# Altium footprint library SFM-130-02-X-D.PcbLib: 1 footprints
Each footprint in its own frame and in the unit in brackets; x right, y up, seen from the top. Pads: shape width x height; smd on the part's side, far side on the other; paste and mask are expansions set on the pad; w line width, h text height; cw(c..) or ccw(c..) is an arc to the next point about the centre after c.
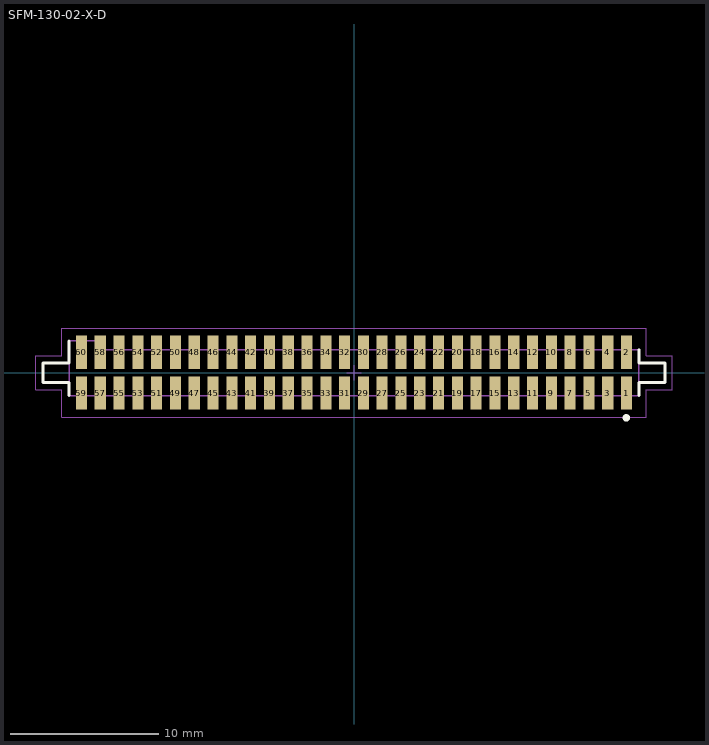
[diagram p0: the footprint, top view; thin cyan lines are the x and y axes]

## SFM-130-02-X-D [mm] "1.27mm pitch, 60 pin, socket header; SMT"
height 4.57
pads (60):
  rect 0.75x2.25 smd mask+0: 1(18.415,-1.375) 2(18.415,1.375) 3(17.145,-1.375) 4(17.145,1.375) 5(15.875,-1.375) 6(15.875,1.375) 7(14.605,-1.375) 8(14.605,1.375) 9(13.335,-1.375) 10(13.335,1.375) 11(12.065,-1.375) 12(12.065,1.375) 13(10.795,-1.375) 14(10.795,1.375) 15(9.525,-1.375) 16(9.525,1.375) 17(8.255,-1.375) 18(8.255,1.375) 19(6.985,-1.375) 20(6.985,1.375) 21(5.715,-1.375) 22(5.715,1.375) 23(4.445,-1.375) 24(4.445,1.375) 25(3.175,-1.375) 26(3.175,1.375) 27(1.905,-1.375) 28(1.905,1.375) 29(0.635,-1.375) 30(0.635,1.375) 31(-0.635,-1.375) 32(-0.635,1.375) 33(-1.905,-1.375) 34(-1.905,1.375) 35(-3.175,-1.375) 36(-3.175,1.375) 37(-4.445,-1.375) 38(-4.445,1.375) 39(-5.715,-1.375) 40(-5.715,1.375) 41(-6.985,-1.375) 42(-6.985,1.375) 43(-8.255,-1.375) 44(-8.255,1.375) 45(-9.525,-1.375) 46(-9.525,1.375) 47(-10.795,-1.375) 48(-10.795,1.375) 49(-12.065,-1.375) 50(-12.065,1.375) 51(-13.335,-1.375) 52(-13.335,1.375) 53(-14.605,-1.375) 54(-14.605,1.375) 55(-15.875,-1.375) 56(-15.875,1.375) 57(-17.145,-1.375) 58(-17.145,1.375) 59(-18.415,-1.375) 60(-18.415,1.375)
Top Overlay:
  circle w0.25: c18.4,-3.05 r0.125
  lines w0.2: -19.25,-1.55 -19.25,-0.65 -21,-0.65 -21,0.65 -19.25,0.65 -19.25,2.15 ; 19.25,-1.55 19.25,-0.65 21,-0.65 21,0.65 19.25,0.65 19.25,1.55
Mechanical 12:
  lines w0.001: -21,-0.65 -19.25,-0.65 -19.25,-1.55 19.25,-1.55 19.25,-0.65 21,-0.65 21,0.65 19.25,0.65 19.25,1.55 -17.2,1.55 -17.2,2.15 -19.25,2.15 -19.25,0.65 -21,0.65 -21,-0.65
Mechanical 13:
  lines w0.1: -19.25,-0.65 -19.25,-1.55 19.25,-1.55 19.25,-0.65 ; -19.25,-0.65 -21,-0.65 -21,0.65 -19.25,0.65 ; -19.25,-0.65 -19.25,0.65 ; -19.25,0.65 -19.25,2.15 -17.2,2.15 -17.2,1.55 19.25,1.55 19.25,0.65 ; 19.25,-0.65 21,-0.65 21,0.65 19.25,0.65 ; 19.25,-0.65 19.25,0.65
  text ".Designator" at 0.127,-0.127 h1.52
Mechanical 15:
  lines w0.05: -0.5,0 0.5,0 ; 0,-0.5 0,0.5 ; -21.5,-1.15 -21.5,1.15 -19.75,1.15 -19.75,3 19.75,3 19.75,1.15 21.5,1.15 21.5,-1.15 19.75,-1.15 19.75,-3 -19.75,-3 -19.75,-1.15 -21.5,-1.15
